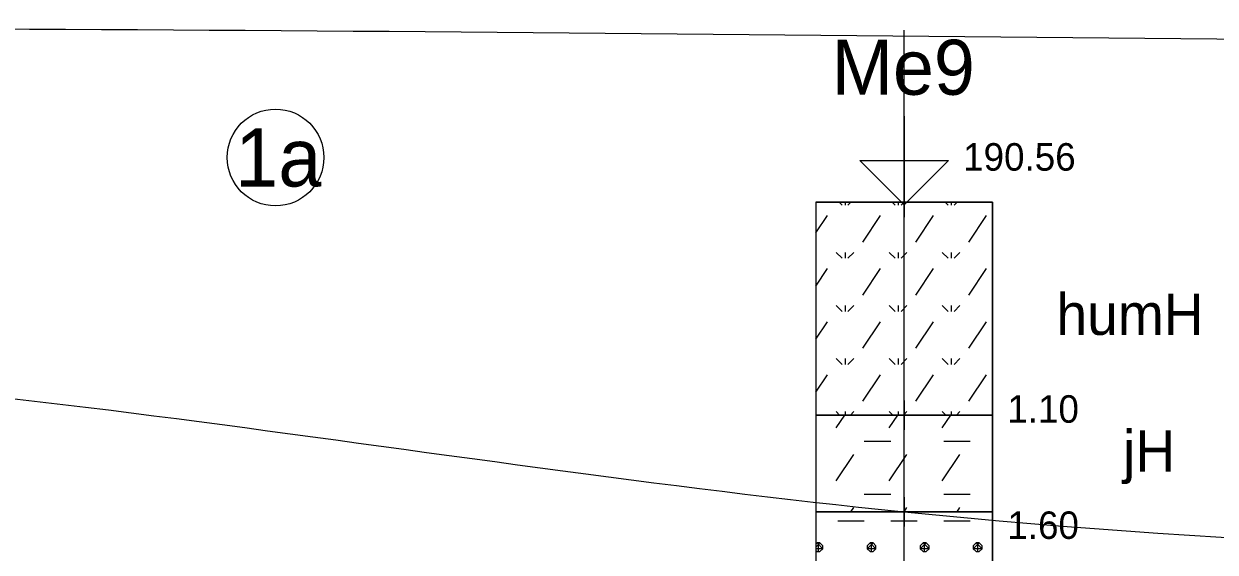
# Model space of a CAD drawing. Extents: x 3042 to 4120, y 576 to 2694.
# Drawn here: x 3484.6 to 3515.4, y 1300.3 to 1313.96 of the extents above; entities that cross this region are included whole.
import ezdxf

# ---------------------------------------------------------------- set-up
doc = ezdxf.new("R2010")
doc.units = 0
for name, color, linetype in [('15', 7, 'Continuous'), ('16', 7, 'Continuous'), ('17', 7, 'Continuous'), ('18', 7, 'Continuous'), ('51', 7, 'Continuous'), ('52', 7, 'Continuous'), ('53', 7, 'Continuous'), ('56', 7, 'Continuous'), ('rozhraní', 7, 'Continuous')]:
    doc.layers.add(name, color=color, linetype=linetype)

msp = doc.modelspace()

# ---------------------------------------------------------------- linework, layer by layer
at = {"layer": '15'}
msp.add_lwpolyline([(3507.357, 1311.568), (3507.357, 1309.282), (3506.214, 1310.425), (3508.5, 1310.425), (3507.357, 1309.282)], dxfattribs=at)
at = {"layer": '18'}
for p, q in [((3507.357, 1268.964), (3507.357, 1313.795)), ((3507.357, 1269.345), (3507.357, 1309.345))]:
    msp.add_line(p, q, dxfattribs=at)
at = {"layer": '51'}
for points in [[(3505.071, 1303.845), (3509.643, 1303.845), (3509.643, 1309.345), (3505.071, 1309.345)], [(3505.071, 1301.345), (3509.643, 1301.345), (3509.643, 1303.845), (3505.071, 1303.845)], [(3505.071, 1297.345), (3509.643, 1297.345), (3509.643, 1301.345), (3505.071, 1301.345)]]:
    msp.add_lwpolyline(points, close=True, dxfattribs=at)
for points in [[(3505.675, 1309.345), (3505.752, 1309.268)], [(3505.828, 1309.345), (3505.828, 1309.268)], [(3505.981, 1309.345), (3505.904, 1309.268)], [(3507.046, 1309.345), (3507.123, 1309.268)], [(3507.2, 1309.345), (3507.2, 1309.268)], [(3507.353, 1309.345), (3507.276, 1309.268)], [(3508.418, 1309.345), (3508.495, 1309.268)], [(3508.571, 1309.345), (3508.571, 1309.268)], [(3508.725, 1309.345), (3508.647, 1309.268)], [(3505.071, 1308.552), (3505.371, 1309.002)], [(3506.285, 1308.316), (3506.742, 1309.002)], [(3507.657, 1308.316), (3508.114, 1309.002)], [(3509.028, 1308.316), (3509.486, 1309.002)], [(3505.599, 1308.049), (3505.752, 1307.897)], [(3505.828, 1308.049), (3505.828, 1307.897)], [(3506.057, 1308.049), (3505.904, 1307.897)], [(3506.971, 1308.049), (3507.123, 1307.897)], [(3507.2, 1308.049), (3507.2, 1307.897)], [(3507.428, 1308.049), (3507.276, 1307.897)], [(3508.343, 1308.049), (3508.495, 1307.897)], [(3508.571, 1308.049), (3508.571, 1307.897)], [(3508.8, 1308.049), (3508.647, 1307.897)], [(3505.071, 1307.18), (3505.371, 1307.63)], [(3506.285, 1306.944), (3506.742, 1307.63)], [(3507.657, 1306.944), (3508.114, 1307.63)], [(3509.028, 1306.944), (3509.486, 1307.63)], [(3505.599, 1306.678), (3505.752, 1306.525)], [(3505.828, 1306.678), (3505.828, 1306.525)], [(3506.057, 1306.678), (3505.904, 1306.525)], [(3506.971, 1306.678), (3507.123, 1306.525)], [(3507.2, 1306.678), (3507.2, 1306.525)], [(3507.428, 1306.678), (3507.276, 1306.525)], [(3508.343, 1306.678), (3508.495, 1306.525)], [(3508.571, 1306.678), (3508.571, 1306.525)], [(3508.8, 1306.678), (3508.647, 1306.525)], [(3505.071, 1305.808), (3505.371, 1306.258)], [(3506.285, 1305.573), (3506.742, 1306.258)], [(3507.657, 1305.573), (3508.114, 1306.258)], [(3509.028, 1305.573), (3509.486, 1306.258)], [(3505.599, 1305.306), (3505.752, 1305.154)], [(3505.828, 1305.306), (3505.828, 1305.154)], [(3506.057, 1305.306), (3505.904, 1305.154)], [(3506.971, 1305.306), (3507.123, 1305.154)], [(3507.2, 1305.306), (3507.2, 1305.154)], [(3507.428, 1305.306), (3507.276, 1305.154)], [(3508.343, 1305.306), (3508.495, 1305.154)], [(3508.571, 1305.306), (3508.571, 1305.154)], [(3508.8, 1305.306), (3508.647, 1305.154)], [(3505.071, 1304.437), (3505.371, 1304.887)], [(3506.285, 1304.201), (3506.742, 1304.887)], [(3507.657, 1304.201), (3508.114, 1304.887)], [(3509.028, 1304.201), (3509.486, 1304.887)], [(3505.599, 1303.934), (3505.688, 1303.845)], [(3505.599, 1303.515), (3505.82, 1303.845)], [(3505.828, 1303.934), (3505.828, 1303.845)], [(3506.057, 1303.934), (3505.968, 1303.845)], [(3506.971, 1303.934), (3507.06, 1303.845)], [(3506.971, 1303.515), (3507.191, 1303.845)], [(3507.2, 1303.934), (3507.2, 1303.845)], [(3507.428, 1303.934), (3507.339, 1303.845)], [(3508.343, 1303.934), (3508.432, 1303.845)], [(3508.343, 1303.515), (3508.563, 1303.845)], [(3508.571, 1303.934), (3508.571, 1303.845)], [(3508.8, 1303.934), (3508.711, 1303.845)], [(3506.323, 1303.172), (3507.009, 1303.172)], [(3508.381, 1303.172), (3509.067, 1303.172)], [(3505.599, 1302.144), (3506.057, 1302.829)], [(3506.971, 1302.144), (3507.428, 1302.829)], [(3508.343, 1302.144), (3508.8, 1302.829)], [(3506.323, 1301.801), (3507.009, 1301.801)], [(3508.381, 1301.801), (3509.067, 1301.801)], [(3505.982, 1301.345), (3506.057, 1301.458)], [(3507.353, 1301.345), (3507.428, 1301.458)], [(3508.725, 1301.345), (3508.8, 1301.458)], [(3505.638, 1301.115), (3506.323, 1301.115)], [(3507.009, 1301.115), (3507.695, 1301.115)], [(3508.381, 1301.115), (3509.067, 1301.115)], [(3505.104, 1300.543), (3505.071, 1300.51)], [(3505.071, 1300.348), (3505.104, 1300.315), (3505.18, 1300.315), (3505.257, 1300.391), (3505.257, 1300.467), (3505.18, 1300.543), (3505.104, 1300.543), (3505.257, 1300.391), (3505.071, 1300.391)], [(3505.071, 1300.434), (3505.18, 1300.543)], [(3505.142, 1300.315), (3505.142, 1300.543)], [(3506.476, 1300.543), (3506.4, 1300.467), (3506.4, 1300.391), (3506.476, 1300.315), (3506.552, 1300.315), (3506.628, 1300.391), (3506.628, 1300.467), (3506.552, 1300.543), (3506.476, 1300.543), (3506.628, 1300.391), (3506.4, 1300.391), (3506.552, 1300.543)], [(3506.514, 1300.315), (3506.514, 1300.543)], [(3507.847, 1300.543), (3507.771, 1300.467), (3507.771, 1300.391), (3507.847, 1300.315), (3507.924, 1300.315), (3508, 1300.391), (3508, 1300.467), (3507.924, 1300.543), (3507.847, 1300.543), (3508, 1300.391), (3507.771, 1300.391), (3507.924, 1300.543)], [(3507.885, 1300.315), (3507.885, 1300.543)], [(3509.219, 1300.543), (3509.143, 1300.467), (3509.143, 1300.391), (3509.219, 1300.315), (3509.295, 1300.315), (3509.371, 1300.391), (3509.371, 1300.467), (3509.295, 1300.543), (3509.219, 1300.543), (3509.371, 1300.391), (3509.143, 1300.391), (3509.295, 1300.543)], [(3509.257, 1300.315), (3509.257, 1300.543)]]:
    msp.add_lwpolyline(points, dxfattribs=at)
at = {"layer": '53'}
for points in [[(3505.071, 1309.345), (3509.643, 1309.345)], [(3505.071, 1309.345), (3505.071, 1269.345)], [(3509.643, 1309.345), (3509.643, 1269.345)], [(3505.071, 1303.845), (3509.643, 1303.845)], [(3505.071, 1301.345), (3509.643, 1301.345)]]:
    msp.add_lwpolyline(points, dxfattribs=at)
at = {"layer": '56'}
for points in [[(3507.357, 1309.726), (3507.357, 1308.964)], [(3506.976, 1309.345), (3507.738, 1309.345)], [(3507.357, 1304.226), (3507.357, 1303.464)], [(3506.976, 1303.845), (3507.738, 1303.845)], [(3507.357, 1301.726), (3507.357, 1300.964)], [(3506.976, 1301.345), (3507.738, 1301.345)]]:
    msp.add_lwpolyline(points, dxfattribs=at)
at = {"layer": 'rozhraní'}
msp.add_circle((3491.104, 1310.503), 1.25, dxfattribs=at)
for points in [[(3433.88, 1313.195), (3467.07, 1313.795), (3526.6, 1313.495), (3558.497, 1313.495)], [(3215.367, 1295.492), (3223.007, 1295.445), (3284.237, 1298.745), (3466.926, 1305.295), (3469.69, 1305.295), (3507.357, 1301.345), (3560.04, 1300.995)]]:
    msp.add_spline(points, degree=3, dxfattribs=at)

# ---------------------------------------------------------------- texts
at = {"layer": '16'}
msp.add_text('Me9', height=1.4224, dxfattribs=at).set_placement((3505.483, 1312.124))
at = {"layer": '17'}
msp.add_text('190.56', height=0.7112, dxfattribs=at).set_placement((3508.881, 1310.163))
at = {"layer": '52'}
for s, height, p in [('humH', 1.0668, (3511.294, 1305.917)), ('1.10', 0.7112, (3510.024, 1303.647)), ('jH', 1.0668, (3513.017, 1302.384)), ('1.60', 0.7112, (3510.024, 1300.644))]:
    msp.add_text(s, height=height, dxfattribs=at).set_placement(p)
at = {"layer": 'rozhraní'}
msp.add_text('1a', height=1.5, dxfattribs=at).set_placement((3490.06, 1309.753))

doc.saveas('drawing.dxf')
